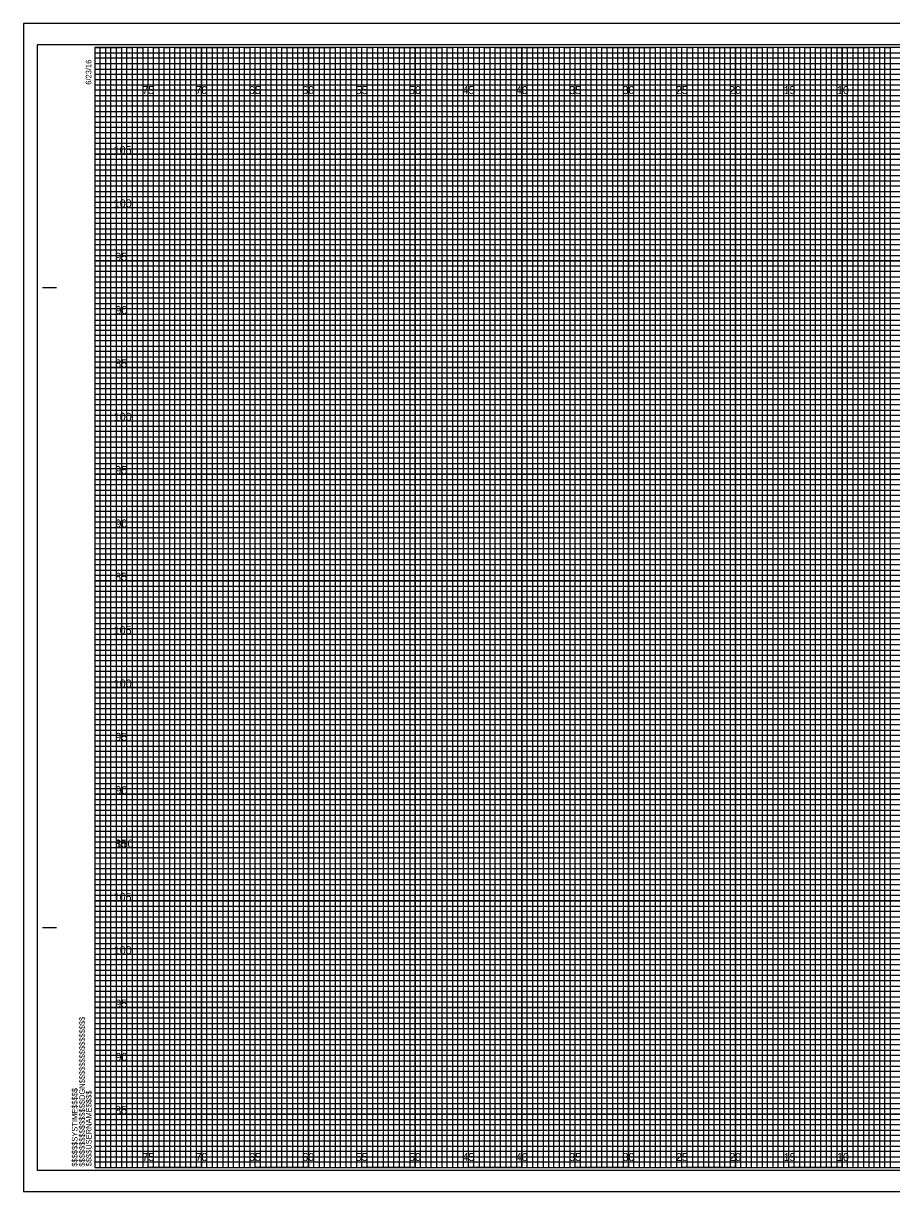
# Model space of a CAD drawing. Extents: x -7 to 182, y -2 to 1647.
# Drawn here: x -6.7 to 74.6, y 327.7 to 437.2 of the extents above; entities that cross this region are included whole.
import ezdxf

# ---------------------------------------------------------------- set-up
doc = ezdxf.new("R2010")
doc.units = 0
for name, color, linetype in [('Exist Cross Section Cell', 7, 'Continuous'), ('Exist XS Ground Line', 7, 'Continuous'), ('Prop CMT Pvmt Course 3', 7, 'Continuous'), ('Prop CMT Pvmt Wedge Surface 1', 7, 'Continuous'), ('Prop CMT Pvmt Wedge Surface 2', 7, 'Continuous'), ('Prop CMT Pvmt Wedge Surface 3', 7, 'Continuous'), ('Prop CMT Shld Paved Course 1', 7, 'Continuous'), ('Prop CMT Shld Paved Course 2', 7, 'Continuous'), ('Prop CMT Shld Paved Course 3', 7, 'Continuous'), ('Prop CMT Slope Grass', 7, 'Continuous'), ('Prop CMT Subgrade Earthwork', 7, 'Continuous')]:
    doc.layers.add(name, color=color, linetype=linetype)

msp = doc.modelspace()

# ---------------------------------------------------------------- linework, layer by layer
at = {"layer": 'Exist XS Ground Line'}
for p, q in [((5, 435), (0, 435)), ((5, 330), (5, 435)), ((15, 435), (10, 435)), ((10, 435), (10, 330)), ((15, 330), (15, 435)), ((25, 435), (20, 435)), ((20, 435), (20, 330)), ((25, 330), (25, 435)), ((35, 435), (30, 435)), ((30, 435), (30, 330)), ((35, 330), (35, 435)), ((45, 435), (40, 435)), ((40, 435), (40, 330)), ((45, 330), (45, 435)), ((55, 435), (50, 435)), ((50, 435), (50, 330)), ((55, 330), (55, 435)), ((65, 435), (60, 435)), ((60, 435), (60, 330)), ((65, 330), (65, 435)), ((75, 435), (70, 435)), ((70, 435), (70, 330)), ((10, 330), (5, 330)), ((20, 330), (15, 330)), ((30, 330), (25, 330)), ((40, 330), (35, 330)), ((50, 330), (45, 330)), ((60, 330), (55, 330)), ((70, 330), (65, 330))]:
    msp.add_line(p, q, dxfattribs=at)
for points in [[(0, 430), (160, 430), (160, 425), (0, 425)], [(0, 420), (160, 420), (160, 415), (0, 415)], [(0, 410), (160, 410), (160, 405), (0, 405)], [(0, 400), (160, 400), (160, 395), (0, 395)], [(0, 390), (160, 390), (160, 385), (0, 385)], [(0, 380), (160, 380), (160, 375), (0, 375)], [(0, 370), (160, 370), (160, 365), (0, 365)], [(0, 360), (160, 360), (160, 355), (0, 355)], [(0, 350), (160, 350), (160, 345), (0, 345)], [(0, 340), (160, 340), (160, 335), (0, 335)]]:
    msp.add_lwpolyline(points, dxfattribs=at)
at = {"layer": 'Prop CMT Pvmt Course 3'}
msp.add_lwpolyline([(-6.7, 327.75), (161.65, 327.75), (161.65, 437.25), (-6.7, 437.25)], close=True, dxfattribs=at)
at = {"layer": 'Prop CMT Pvmt Wedge Surface 1'}
for p, q in [((0, 434.5), (130, 434.5)), ((130, 433.99), (0, 433.99)), ((0, 433.99), (0, 433.5)), ((0, 433.5), (130, 433.5)), ((130, 432.94), (0, 432.94)), ((0, 432.94), (0, 432)), ((0, 432), (160, 432))]:
    msp.add_line(p, q, dxfattribs=at)
for points in [[(0, 431.5), (135, 431.5), (160, 431.5), (160, 431), (0, 431)], [(0, 430.5), (160, 430.5), (160, 429.5), (0, 429.5)], [(0, 429), (160, 429), (160, 428.5), (0, 428.49)], [(0, 428), (160, 428), (160, 427), (0, 427)], [(0, 426.5), (160, 426.5), (160, 426), (0, 426)], [(0, 425.5), (160, 425.5), (160, 424.5), (0, 424.5)], [(0, 424), (160, 424), (160, 423.5), (0, 423.5)], [(0, 423), (160, 423), (160, 422), (0, 422)], [(0, 421.5), (160, 421.5), (160, 421), (0, 421)], [(0, 420.5), (160, 420.5), (160, 419.5), (0, 419.5)], [(0, 419), (160, 419), (160, 418.5), (0, 418.5)], [(0, 418), (160, 418), (160, 416.98), (160, 416.5), (160, 416), (0, 416)], [(0, 417), (160, 417), (160, 416.5), (0, 416.5)], [(0, 415.5), (160, 415.5), (160, 414.5), (0, 414.51)], [(0, 414.51), (160, 414.5), (160, 414), (0, 414)], [(0, 413.5), (160, 413.5), (160, 413), (0, 413)], [(0, 412), (160, 412), (160, 411.5), (0, 411.5)], [(0, 411), (160, 411), (160, 410.5), (0, 410.5)], [(-0.04, 409.44), (160, 409.44), (160, 408.94), (-0.04, 408.94)], [(0, 408.5), (160, 408.5), (160, 408), (0, 408)], [(0, 407), (160, 407), (160, 406.5), (0, 406.5)], [(0, 406), (160, 406), (160, 405.5), (0, 405.5)], [(0, 404.5), (160, 404.5), (160, 404), (0, 404)], [(0, 403.5), (160, 403.5), (160, 403), (0, 403)], [(0, 402), (160, 402), (160, 401.5), (0, 401.5)], [(0, 401), (160, 401), (160, 400.5), (0, 400.5)], [(0, 399.5), (160, 399.5), (160, 398.99), (0, 399)], [(0, 398.5), (160, 398.5), (160, 398), (0, 398)], [(0, 397), (160, 397), (160, 396.5), (0, 396.5)], [(0, 396), (160, 396), (160, 395.5), (0, 395.5)], [(0, 394.5), (160, 394.5), (160, 394), (0, 394)], [(0, 393.5), (160, 393.5), (160, 393), (0, 393)], [(0, 392), (160, 392), (160, 391.5), (0, 391.5)], [(0, 391), (160, 391), (160, 390.5), (0, 390.5)], [(0, 389.5), (160, 389.5), (160, 389), (0, 389)], [(0, 388.5), (160.03, 388.45), (160, 388), (0, 388)], [(0, 387), (160, 387), (160, 386.5), (0, 386.5)], [(0, 386), (160, 386), (160, 385.5), (0, 385.5)], [(0, 384.5), (160, 384.5), (160, 384), (0, 384)], [(0, 383.5), (160, 383.5), (160, 383), (0, 383)], [(0, 382), (160, 382), (160, 381.5), (0, 381.5)], [(0, 381), (160, 381), (160, 380.5), (0, 380.5)], [(0, 379.5), (160, 379.5), (160, 379), (0, 379)], [(0, 378.5), (160, 378.5), (160, 378), (0, 378)], [(0, 377), (160, 377), (160, 376.5), (0, 376.5)], [(0, 376), (160, 376), (160, 375.5), (0, 375.5)], [(0, 374.5), (160, 374.5), (160, 374), (0, 374)], [(0, 373.5), (160, 373.5), (160, 373), (0, 373)], [(0, 372), (160, 372), (160, 371.5), (0, 371.5)], [(0, 371), (160, 371), (160, 370.5), (0, 370.5)], [(0, 369.5), (160, 369.5), (160, 368.99), (0, 369)], [(0, 368.5), (160, 368.5), (160, 368), (0, 368)], [(0, 367), (160, 367), (160, 366.5), (0, 366.5)], [(0, 366), (160, 366), (160, 365.5), (0, 365.5)], [(0, 364.5), (160, 364.5), (160, 364), (0, 364)], [(0, 363.5), (160, 363.5), (160, 363), (0, 363)], [(0, 362), (160, 362), (160, 361.5), (0, 361.5)], [(0, 361), (160, 361), (160, 360.5), (0, 360.5)], [(0, 359.5), (160, 359.5), (160, 359), (0, 359)], [(0, 358.5), (160.03, 358.45), (160, 358), (0, 358)], [(0, 357), (160, 357), (160, 356.5), (0, 356.5)], [(0, 356), (160, 356), (160, 355.5), (0, 355.5)], [(0, 354.5), (160, 354.5), (160, 354), (0, 354)], [(0, 353.5), (160, 353.5), (160, 353), (0, 353)], [(0, 352), (160, 352), (160, 351.5), (0, 351.5)], [(0, 351), (160, 351), (160, 350.5), (0, 350.5)], [(0, 349.5), (160, 349.5), (160, 349), (0, 349)], [(0, 348.5), (160, 348.5), (160, 348), (0, 348)], [(0, 347), (160, 347), (160, 346.5), (0, 346.5)], [(0, 346), (160, 346), (160, 345.5), (0, 345.5)], [(0, 344.5), (160, 344.5), (160, 344), (0, 344)], [(0, 343.5), (160, 343.5), (160, 343), (0, 343)], [(0, 342), (160, 342), (160, 341.5), (0, 341.5)], [(0, 341), (160, 341), (160, 340.5), (0, 340.5)], [(0, 339.5), (160, 339.5), (160, 339), (0, 339)], [(0, 338.5), (160, 338.5), (160, 338), (0, 338)], [(0, 337), (160, 337), (160, 336.5), (0, 336.5)], [(0, 336), (160, 336), (160, 335.5), (0, 335.5)], [(0, 334.5), (160, 334.5), (160, 334), (0, 334)], [(0, 333.5), (160, 333.5), (160, 333), (0, 333)], [(0, 332), (160, 332), (160, 331.5), (0, 331.5)], [(0, 331), (160, 331), (160, 330.5), (0, 330.5)]]:
    msp.add_lwpolyline(points, dxfattribs=at)
at = {"layer": 'Prop CMT Pvmt Wedge Surface 2'}
for p, q in [((-4.9, 412.5), (-3.65, 412.5)), ((-4.85, 412.5), (-3.6, 412.5)), ((-4.9, 352.5), (-3.65, 352.5)), ((-4.85, 352.5), (-3.6, 352.5)), ((0, 330), (0, 330)), ((0, 330), (0, 330)), ((0, 330), (0, 330)), ((0, 330), (0, 330)), ((0, 330), (0, 330)), ((0, 330), (0, 330)), ((0, 330), (0, 330))]:
    msp.add_line(p, q, dxfattribs=at)
msp.add_lwpolyline([(160, 435), (0, 435), (0, 330), (160, 330)], close=True, dxfattribs=at)
at = {"layer": 'Prop CMT Pvmt Wedge Surface 3'}
for points in [[(0, 330), (0.5, 330), (0.5, 435), (1, 435), (1, 330)], [(1, 330), (1.5, 330), (1.5, 435), (2, 435), (2, 330)], [(2.5, 330), (3, 330), (3, 435), (3.5, 435), (3.5, 330)], [(3.5, 330), (4, 330), (4, 435), (4.5, 435), (4.5, 330)], [(5, 330), (5.5, 330), (5.5, 435), (6, 435), (6, 330)], [(6, 330), (6.5, 330), (6.5, 435), (7, 435), (7, 330)], [(7.5, 330), (8, 330), (8, 435), (8.5, 435), (8.5, 330)], [(8.5, 330), (9, 330), (9, 435), (9.5, 435), (9.5, 330)], [(10, 330), (10.5, 330), (10.5, 435), (11, 435), (11, 330)], [(11, 330), (11.5, 330), (11.5, 435), (12, 435), (12, 330)], [(12.5, 330), (13, 330), (13, 435), (13.5, 435), (13.5, 330)], [(13.5, 330), (14, 330), (14, 435), (14.5, 435), (14.5, 330)], [(15, 330), (15.5, 330), (15.5, 435), (16, 435), (16, 330)], [(16, 330), (16.5, 330), (16.5, 435), (17, 435), (17, 330)], [(17.5, 330), (18, 330), (18, 435), (18.5, 435), (18.5, 330)], [(18.5, 330), (19, 330), (19, 435), (19.5, 435), (19.5, 330)], [(20, 330), (20.5, 330), (20.5, 435), (21, 435), (21, 330)], [(21, 330), (21.5, 330), (21.5, 435), (22, 435), (22, 330)], [(22.5, 330), (23, 330), (23, 435), (23.5, 435), (23.5, 330)], [(23.5, 330), (24, 330), (24, 435), (24.5, 435), (24.5, 330)], [(25, 330), (25.5, 330), (25.5, 435), (26, 435), (26, 330)], [(26, 330), (26.5, 330), (26.5, 435), (27, 435), (27, 330)], [(27.5, 330), (28, 330), (28, 435), (28.5, 435), (28.5, 330)], [(28.5, 330), (29, 330), (29, 435), (29.5, 435), (29.5, 330)], [(30, 330), (30.5, 330), (30.5, 435), (31, 435), (31, 330)], [(31, 330), (31.5, 330), (31.5, 435), (32, 435), (32, 330)], [(32.5, 330), (33, 330), (33, 435), (33.5, 435), (33.5, 330)], [(33.5, 330), (34, 330), (34, 435), (34.5, 435), (34.5, 330)], [(35, 330), (35.5, 330), (35.5, 435), (36, 435), (36, 330)], [(36, 330), (36.5, 330), (36.5, 435), (37, 435), (37, 330)], [(37.5, 330), (38, 330), (38, 435), (38.5, 435), (38.5, 330)], [(38.5, 330), (39, 330), (39, 435), (39.5, 435), (39.5, 330)], [(40, 330), (40.5, 330), (40.5, 435), (41, 435), (41, 330)], [(41, 330), (41.5, 330), (41.5, 435), (42, 435), (42, 330)], [(42.5, 330), (43, 330), (43, 435), (43.5, 435), (43.5, 330)], [(43.5, 330), (44, 330), (44, 435), (44.5, 435), (44.5, 330)], [(45, 330), (45.5, 330), (45.5, 435), (46, 435), (46, 330)], [(46, 330), (46.5, 330), (46.5, 435), (47, 435), (47, 330)], [(47.5, 330), (48, 330), (48, 435), (48.5, 435), (48.5, 330)], [(48.5, 330), (49, 330), (49, 435), (49.5, 435), (49.5, 330)], [(50, 330), (50.5, 330), (50.5, 435), (51, 435), (51, 330)], [(51, 330), (51.5, 330), (51.5, 435), (52, 435), (52, 330)], [(52.5, 330), (53, 330), (53, 435), (53.5, 435), (53.5, 330)], [(53.5, 330), (54, 330), (54, 435), (54.5, 435), (54.5, 330)], [(55, 330), (55.5, 330), (55.5, 435), (56, 435), (56, 330)], [(56, 330), (56.5, 330), (56.5, 435), (57, 435), (57, 330)], [(57.5, 330), (58, 330), (58, 435), (58.5, 435), (58.5, 330)], [(58.5, 330), (59, 330), (59, 435), (59.5, 435), (59.5, 330)], [(60, 330), (60.5, 330), (60.5, 435), (61, 435), (61, 330)], [(61, 330), (61.5, 330), (61.5, 435), (62, 435), (62, 330)], [(62.5, 330), (63, 330), (63, 435), (63.5, 435), (63.5, 330)], [(63.5, 330), (64, 330), (64, 435), (64.5, 435), (64.5, 330)], [(65, 330), (65.5, 330), (65.5, 435), (66, 435), (66, 330)], [(66, 330), (66.5, 330), (66.5, 435), (67, 435), (67, 330)], [(67.5, 330), (68, 330), (68, 435), (68.5, 435), (68.5, 330)], [(68.5, 330), (69, 330), (69, 435), (69.5, 435), (69.5, 330)], [(70, 330), (70.5, 330), (70.5, 435), (71, 435), (71, 330)], [(71, 330), (71.5, 330), (71.5, 435), (72, 435), (72, 330)], [(72.5, 330), (73, 330), (73, 435), (73.5, 435), (73.5, 330)], [(73.5, 330), (74, 330), (74, 435), (74.5, 435), (74.5, 330)]]:
    msp.add_lwpolyline(points, dxfattribs=at)
at = {"layer": 'Prop CMT Shld Paved Course 1'}
for p, q in [((5, 330), (5, 435)), ((10, 330), (10, 435)), ((15, 330), (15, 435)), ((20, 330), (20, 435)), ((25, 330), (25, 435)), ((30, 330), (30, 435)), ((35, 330), (35, 435)), ((40, 330), (40, 435)), ((45, 330), (45, 435)), ((50, 330), (50, 435)), ((55, 330), (55, 435)), ((60, 330), (60, 435)), ((65, 330), (65, 435)), ((70, 330), (70, 435)), ((0, 430), (160, 430)), ((0, 425), (160, 425)), ((0, 420), (160, 420)), ((0, 415), (160, 415)), ((0, 410), (160, 410)), ((0, 405), (160, 405)), ((0, 400), (160, 400)), ((0, 395), (160, 395)), ((0, 390), (160, 390)), ((0, 385), (160, 385)), ((0, 380), (160, 380)), ((0, 375), (160, 375)), ((0, 370), (160, 370)), ((0, 365), (160, 365)), ((0, 360), (160, 360)), ((0, 355), (160, 355)), ((0, 350), (160, 350)), ((0, 345), (160, 345)), ((0, 340), (160, 340)), ((0, 335), (160, 335))]:
    msp.add_line(p, q, dxfattribs=at)
at = {"layer": 'Prop CMT Shld Paved Course 2'}
for p, q in [((161.65, 437.25), (-6.7, 437.25)), ((-6.7, 437.25), (-6.7, 327.75)), ((-6.7, 327.75), (161.65, 327.75))]:
    msp.add_line(p, q, dxfattribs=at)
at = {"layer": 'Prop CMT Slope Grass'}
msp.add_lwpolyline([(-5.4, 329.75), (161.2, 329.75), (161.2, 435.25), (-5.4, 435.25)], close=True, dxfattribs=at)
at = {"layer": 'Prop CMT Subgrade Earthwork'}
for points in [[(0, 435), (2.5, 435), (2.5, 330), (7.5, 330), (7.5, 435), (12.5, 435), (12.5, 330), (17.5, 330), (17.5, 435), (22.5, 435), (22.5, 330), (27.5, 330), (27.5, 435), (32.5, 435), (32.5, 330), (37.5, 330), (37.5, 435), (42.5, 435), (42.5, 330), (47.5, 330), (47.5, 435), (52.5, 435), (52.5, 330), (57.5, 330), (57.5, 435), (62.5, 435), (62.5, 330), (67.5, 330), (67.5, 435), (72.5, 435), (72.5, 330), (77.5, 330)], [(0, 432.5), (137.5, 432.5)], [(0, 422.5), (160, 422.5), (160, 427.5), (0, 427.5)], [(0, 412.5), (160, 412.5), (160, 417.5), (0, 417.5)], [(0, 402.5), (160, 402.5), (160, 407.5), (0, 407.5)], [(0, 392.5), (160, 392.5), (160, 397.5), (0, 397.5)], [(0, 382.5), (160, 382.5), (160, 387.5), (0, 387.5)], [(0, 372.5), (160, 372.5), (160, 377.5), (0, 377.5)], [(0, 362.5), (160, 362.5), (160, 367.5), (0, 367.5)], [(0, 352.5), (160, 352.5), (160, 357.5), (0, 357.5)], [(0, 342.5), (160, 342.5), (160, 347.5), (0, 347.5)], [(0, 332.5), (160, 332.5), (160, 337.5), (0, 337.5)]]:
    msp.add_lwpolyline(points, dxfattribs=at)

# ---------------------------------------------------------------- texts
at = {"layer": 'Exist Cross Section Cell'}
for s, p in [('75', (4.44, 430.62)), ('70', (9.43, 430.62)), ('65', (14.44, 430.62)), ('60', (19.43, 430.62)), ('55', (24.44, 430.62)), ('50', (29.43, 430.62)), ('45', (34.44, 430.62)), ('40', (39.43, 430.62)), ('35', (44.44, 430.62)), ('30', (49.43, 430.62)), ('25', (54.44, 430.62)), ('20', (59.43, 430.62)), ('15', (64.53, 430.62)), ('10', (69.52, 430.62)), ('75', (4.44, 330.62)), ('70', (9.43, 330.62)), ('65', (14.44, 330.62)), ('60', (19.43, 330.62)), ('55', (24.44, 330.62)), ('50', (29.43, 330.62)), ('45', (34.44, 330.62)), ('40', (39.43, 330.62)), ('35', (44.44, 330.62)), ('30', (49.43, 330.62)), ('25', (54.44, 330.62)), ('20', (59.43, 330.62)), ('15', (64.53, 330.62)), ('10', (69.52, 330.62))]:
    msp.add_text(s, height=0.75, dxfattribs=at).set_placement(p)
at = {"layer": 'Prop CMT Pvmt Wedge Surface 2'}
for s, p in [('6/23/16', (-0.33, 431.5)), ('$$$$$$$$$$$$$$$$DGN$$$$$$$$$$$$$$$$', (-0.94, 330.09)), ('$$$$$$SYSTIME$$$$$', (-1.63, 330.09)), ('$$$$USERNAME$$$$', (-0.31, 330.12))]:
    msp.add_text(s, height=0.525, rotation=90, dxfattribs=at).set_placement(p)
at = {"layer": 'Prop CMT Shld Paved Course 3'}
for s, p in [('105', (1.76, 425)), ('100', (1.77, 420)), ('95', (1.92, 415)), ('90', (1.93, 410)), ('85', (1.91, 405)), ('100', (1.77, 400)), ('95', (1.92, 395)), ('90', (1.93, 390)), ('85', (1.91, 385)), ('105', (1.76, 380)), ('100', (1.77, 375)), ('95', (1.92, 370)), ('90', (1.93, 365)), ('85', (1.91, 360)), ('110', (1.94, 360)), ('105', (1.76, 355)), ('100', (1.77, 350)), ('95', (1.92, 345)), ('90', (1.93, 340)), ('85', (1.91, 335))]:
    msp.add_text(s, height=0.75, dxfattribs=at).set_placement(p)

doc.saveas('drawing.dxf')
